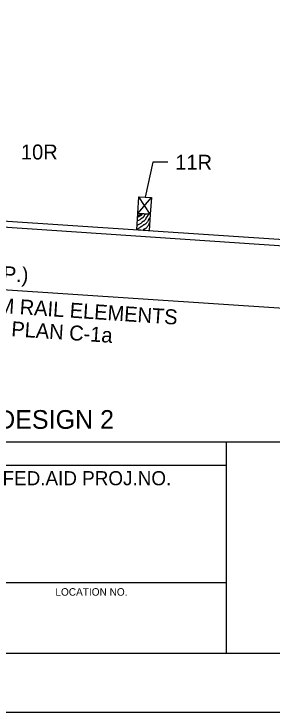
# Model space of a CAD drawing. Extents: x 1312564.2 to 1312581.5, y 1207298.4 to 1207352.6.
# Drawn here: x 1312571.742 to 1312573.115, y 1207298.421 to 1207302.136 of the extents above; entities that cross this region are included whole.
import ezdxf

# ---------------------------------------------------------------- set-up
doc = ezdxf.new("R2010")
doc.units = 0
for name, color, linetype in [('Level 1', 7, 'Continuous'), ('Level 13', 7, 'Continuous'), ('Level 14', 7, 'Continuous'), ('Level 15', 7, 'Continuous'), ('Level 2', 7, 'Continuous'), ('Level 20', 7, 'Continuous'), ('SH_GI_SheetTextInCells', 7, 'Continuous')]:
    doc.layers.add(name, color=color, linetype=linetype)

msp = doc.modelspace()

# ---------------------------------------------------------------- linework, layer by layer
at = {"layer": 'Level 1'}
for p, q in [((1312565.4154872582, 1207299.8593171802), (1312581.1654872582, 1207299.8593171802)), ((1312572.8721328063, 1207298.7334171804), (1312572.8721328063, 1207299.8593171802)), ((1312565.4154872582, 1207299.7342171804), (1312572.8721328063, 1207299.7342171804)), ((1312572.8721328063, 1207299.1087171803), (1312570.8621010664, 1207299.1087171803)), ((1312565.4154872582, 1207298.7334171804), (1312581.1654872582, 1207298.7334171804))]:
    msp.add_line(p, q, dxfattribs=at)
at = {"layer": 'Level 13'}
for points in [[(1312572.458750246, 1207301.0708643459), (1312572.455660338, 1207301.0659267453), (1312572.453794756, 1207301.0630224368), (1312572.451871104, 1207301.0601545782), (1312572.4499075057, 1207301.057315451), (1312572.447922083, 1207301.0544973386), (1312572.4476168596, 1207301.054172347), (1312572.447241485, 1207301.0539224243), (1312572.4463717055, 1207301.0535499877), (1312572.4454955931, 1207301.053184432), (1312572.4447959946, 1207301.05263016), (1312572.444454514, 1207301.0521349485), (1312572.4441647, 1207301.0516107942), (1312572.4437117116, 1207301.050491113), (1312572.4431137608, 1207301.0480744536), (1312572.4425483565, 1207301.0456274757), (1312572.4418726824, 1207301.0439211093), (1312572.441561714, 1207301.0433974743), (1312572.4398185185, 1207301.040915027), (1312572.4379265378, 1207301.0385400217), (1312572.4358744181, 1207301.0362936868), (1312572.433650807, 1207301.03419725), (1312572.4325018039, 1207301.033354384), (1312572.4312443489, 1207301.032674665), (1312572.428556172, 1207301.0315896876), (1312572.425890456, 1207301.0305123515), (1312572.424661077, 1207301.0298421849), (1312572.4235513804, 1207301.029012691), (1312572.423129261, 1207301.0284242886), (1312572.4228364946, 1207301.0277132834), (1312572.4225239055, 1207301.027022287), (1312572.4220423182, 1207301.0264939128), (1312572.3960370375, 1207301.0096222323)], [(1312572.4419179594, 1207301.0719864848), (1312572.4375678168, 1207301.06571185), (1312572.437334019, 1207301.0654926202), (1312572.4370304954, 1207301.0653664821), (1312572.4363055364, 1207301.0652711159), (1312572.4355754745, 1207301.065181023), (1312572.4350228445, 1207301.0648514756), (1312572.4348658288, 1207301.0646176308), (1312572.4347357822, 1207301.0643696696), (1312572.4345419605, 1207301.063838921), (1312572.434316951, 1207301.0626907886), (1312572.4341136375, 1207301.061527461), (1312572.4339469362, 1207301.0609777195), (1312572.4336978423, 1207301.0604693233), (1312572.432804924, 1207301.0590529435), (1312572.4318844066, 1207301.057648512), (1312572.4299231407, 1207301.054911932), (1312572.4265402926, 1207301.0511244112), (1312572.4259100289, 1207301.0505447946), (1312572.4252576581, 1207301.0499829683), (1312572.4243479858, 1207301.04935391), (1312572.4233586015, 1207301.0488686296), (1312572.4212518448, 1207301.0481449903), (1312572.4191596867, 1207301.0474432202), (1312572.4177338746, 1207301.04670937), (1312572.4175157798, 1207301.0465571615), (1312572.4173044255, 1207301.0463944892), (1312572.4167305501, 1207301.0457736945), (1312572.4162396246, 1207301.0450489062), (1312572.4157269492, 1207301.0443483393), (1312572.4150878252, 1207301.0438002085), (1312572.3993043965, 1207301.0346122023)], [(1312572.425125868, 1207301.073105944), (1312572.423577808, 1207301.0708696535), (1312572.4232341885, 1207301.070357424), (1312572.42289898, 1207301.0698311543), (1312572.4208993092, 1207301.0666021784), (1312572.4193610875, 1207301.0646742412), (1312572.4174387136, 1207301.063224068), (1312572.41106472, 1207301.0599273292), (1312572.4004547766, 1207301.0544396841)], [(1312572.417170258, 1207301.073636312), (1312572.4167864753, 1207301.0718821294), (1312572.4163607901, 1207301.070166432), (1312572.4157734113, 1207301.068599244), (1312572.415381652, 1207301.0679057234), (1312572.4151547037, 1207301.0675874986), (1312572.4150326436, 1207301.0674362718), (1312572.4149693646, 1207301.067362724), (1312572.41493715, 1207301.0673264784), (1312572.4149208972, 1207301.0673084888), (1312572.4149045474, 1207301.067290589), (1312572.414600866, 1207301.0669774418), (1312572.4142803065, 1207301.0666797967), (1312572.4135918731, 1207301.066127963), (1312572.4120489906, 1207301.0651767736), (1312572.4084851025, 1207301.0637135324), (1312572.4046378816, 1207301.062510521), (1312572.4027408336, 1207301.0618846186), (1312572.400932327, 1207301.0611773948)], [(1312572.4655438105, 1207301.0528700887), (1312572.4611320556, 1207301.046396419), (1312572.460471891, 1207301.0457311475), (1312572.4596596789, 1207301.0452069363), (1312572.4588418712, 1207301.0446882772), (1312572.458164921, 1207301.044039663), (1312572.4576046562, 1207301.043095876), (1312572.457205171, 1207301.0420694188), (1312572.4566887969, 1207301.0398667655), (1312572.4562163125, 1207301.0376282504), (1312572.455650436, 1207301.0360440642), (1312572.455388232, 1207301.0355504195), (1312572.4523281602, 1207301.0306629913), (1312572.4489607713, 1207301.0259996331), (1312572.4452030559, 1207301.0216288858), (1312572.4431518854, 1207301.01957466), (1312572.4420786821, 1207301.0185840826), (1312572.4409720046, 1207301.01761929), (1312572.4395613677, 1207301.0166107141), (1312572.438032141, 1207301.0158064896), (1312572.4347823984, 1207301.0145494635), (1312572.4315517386, 1207301.0133249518), (1312572.4293391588, 1207301.0121131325), (1312572.428669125, 1207301.0116096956), (1312572.4279507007, 1207301.0108480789), (1312572.4273249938, 1207301.009971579), (1312572.4266794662, 1207301.0091154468), (1312572.4259015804, 1207301.0084149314), (1312572.4221779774, 1207301.006131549), (1312572.4183694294, 1207301.0039699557), (1312572.4145703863, 1207301.0017890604), (1312572.410875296, 1207300.9994477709), (1312572.3952374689, 1207300.9887594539)], [(1312572.46361248, 1207301.0238997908), (1312572.4628935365, 1207301.022850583), (1312572.4625916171, 1207301.0224916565), (1312572.4622335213, 1207301.0221849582), (1312572.4614217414, 1207301.021660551), (1312572.4606040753, 1207301.0211419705), (1312572.460238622, 1207301.0208425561), (1312572.459926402, 1207301.0204938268), (1312572.4593649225, 1207301.0195506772), (1312572.4589648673, 1207301.0185245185), (1312572.4584486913, 1207301.0163217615), (1312572.4579771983, 1207301.0140827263), (1312572.457632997, 1207301.0130112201), (1312572.4571497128, 1207301.0120045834), (1312572.4564082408, 1207301.0107659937), (1312572.4556501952, 1207301.0095391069), (1312572.4506974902, 1207301.002471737), (1312572.4469366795, 1207300.9981032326), (1312572.4448944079, 1207300.9960425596), (1312572.4438292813, 1207300.9950461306), (1312572.4427334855, 1207300.9940734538), (1312572.4413119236, 1207300.9930837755), (1312572.4397340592, 1207300.9923414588), (1312572.4363555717, 1207300.9912404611), (1312572.4330903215, 1207300.9900535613), (1312572.4316540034, 1207300.989203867), (1312572.430430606, 1207300.9880638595), (1312572.4292366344, 1207300.9865601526)]]:
    msp.add_spline(points, degree=3, dxfattribs=at)
at = {"layer": 'Level 14'}
for p, q in [((1312572.4005306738, 1207301.0747456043), (1312572.4725933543, 1207301.1586144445)), ((1312572.4667080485, 1207301.0703338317), (1312572.4064159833, 1207301.1630262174))]:
    msp.add_line(p, q, dxfattribs=at)
at = {"layer": 'Level 15'}
for p, q in [((1312572.480305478, 1207301.346759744), (1312572.4395046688, 1207301.1608203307)), ((1312572.5600341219, 1207301.346759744), (1312572.480305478, 1207301.346759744)), ((1312568.209466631, 1207301.2673344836), (1312575.5205605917, 1207300.7799342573)), ((1312568.207260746, 1207301.234245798), (1312575.5205605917, 1207300.7466985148)), ((1312569.9194786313, 1207300.7877419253), (1312573.229335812, 1207300.5670875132))]:
    msp.add_line(p, q, dxfattribs=at)
for points in [[(1312572.4667080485, 1207301.0703338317), (1312572.4005306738, 1207301.0747456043), (1312572.4064159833, 1207301.1630262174), (1312572.4725933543, 1207301.1586144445)], [(1312572.460822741, 1207300.982053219), (1312572.3946453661, 1207300.9864649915), (1312572.4005306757, 1207301.0747456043), (1312572.4667080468, 1207301.0703338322)]]:
    msp.add_lwpolyline(points, close=True, dxfattribs=at)
at = {"layer": 'Level 2'}
msp.add_lwpolyline([(1312564.4779872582, 1207298.4209171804), (1312581.4779872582, 1207298.4209171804), (1312581.4779872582, 1207309.4209171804), (1312564.4779872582, 1207309.4209171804)], close=True, dxfattribs=at)

# ---------------------------------------------------------------- texts
at = {"layer": 'Level 20'}
for s, height, p in [('10R', 0.07972865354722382, (1312571.7787349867, 1207301.3616389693)), ('11R', 0.07972865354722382, (1312572.5998984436, 1207301.3068954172)), ('BEAM GUARDRAIL BULL NOSE TERMINAL - DESIGN 2', 0.0996608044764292, (1312568.845170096, 1207299.9282150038))]:
    msp.add_text(s, height=height, dxfattribs=at).set_placement(p)
for s, p in [('25\' - 0" (TYP.)', (1312571.149119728, 1207300.7505815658)), ('STANDARD THRIE BEAM RAIL ELEMENTS', (1312570.47573092, 1207300.62409583)), ('STANDARD PLAN C-1a', (1312571.1109569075, 1207300.4620476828))]:
    msp.add_text(s, height=0.07972865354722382, rotation=356.20000000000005, dxfattribs=at).set_placement(p)
at = {"layer": 'SH_GI_SheetTextInCells'}
for s, height, p in [('FED.AID PROJ.NO.', 0.07505999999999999, (1312571.6807192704, 1207299.6279172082)), ('LOCATION NO.', 0.04003199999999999, (1312571.9619610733, 1207299.0401223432))]:
    msp.add_text(s, height=height, dxfattribs=at).set_placement(p)

doc.saveas('drawing.dxf')
